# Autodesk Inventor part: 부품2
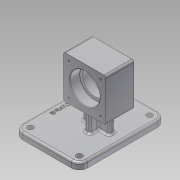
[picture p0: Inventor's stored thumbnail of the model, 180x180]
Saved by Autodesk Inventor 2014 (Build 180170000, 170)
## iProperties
Created: 2020-11
Part Number: 부품2
Material: 알루미늄 6061
Document SubType Name: Modeling
Designer: NET
Density: 2.71 g/cm^3
Appearance: 알루미늄 - 평지
Mass: 683.566 g
Surface Area: 546.675 cm^2
Volume: 252.238 cm^3
Author: NET
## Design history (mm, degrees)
sketch "스케치1"
  geometry: L1 (0, 0)-(64, 0); L2 (64, 0)-(64, 64); L3 (64, 64)-(0, 64); L4 (0, 64)-(0, 0)
  constraints: 8 end point, 2 parallel, 1 horizontal, 1 perpendicular
  dimensions: "d0" = 64 distance of L2.end L3.end; "d1" = 64 distance of L1.end L2.end
extrude "돌출1" new body sketch "스케치1" distance "d2" = 42; taper "d3" = 0 deg
sketch "스케치2"
  geometry: L1 (0, 0)-(0, 64) reference; L2 (0, 64)-(-64, 64) reference; L3 (-64, 64)-(-64, 0) reference; L4 (-64, 0)-(0, 0) reference; L5 (-32, 64)-(-32, 0); L6 (-64, 32)-(0, 32); C1 r 18 at (-32, 32)
  constraints: 5 midpoint, 4 end point, 1 centre point
  dimensions: "d4" = 36 diameter of C1
extrude "돌출2" cut sketch "스케치2" stored distance "d5" = 42; taper "d6" = 0 deg
sketch "스케치3"
  geometry: C1 r 18 at (-32, 32) reference; C2 r 22.5 at (-32, 32)
  constraints: 1 centre point, 1 coincident
  dimensions: "d7" = 45 diameter of C2
extrude "돌출3" cut sketch "스케치3" distance "d8" = 15; taper "d9" = 0 deg
sketch "스케치4"
  geometry: C1 r 18 at (32, 32) reference; C2 r 21 at (32, 32)
  constraints: 1 centre point, 1 coincident
  dimensions: "d10" = 42 diameter of C2
extrude "돌출4" cut sketch "스케치4" distance "d11" = 15; taper "d12" = 0 deg
node "작업 평면1"
sketch "스케치5"
  geometry: L1 (0, 0)-(0, 64) reference; L2 (0, 64)-(-42, 64) reference; L3 (-42, 0)-(-42, 64) reference; L4 (0, 0)-(-42, 0) reference; L5 (-21, 64)-(-21, 0); L6 (0, 32)-(-42, 32); L7 (44, -30)-(-86, -30); L8 (-86, -30)-(-86, 68); L9 (-86, 68)-(44, 68); L10 (44, 68)-(44, -30); L11 (44, -30)-(-86, 68); L12 (-86, -30)-(44, 68); 2 further points
  constraints: 16 end point, 6 midpoint, 2 parallel, 1 horizontal, 1 perpendicular, 1 point on line
  dimensions: "d14" = 130 distance of L8.end L9.end; "d15" = 98 distance of L7.end L8.end; "d16" = 62 vertical distance of L7.end L6.end
extrude "돌출5" join sketch "스케치5" distance "d17" = 10; taper "d18" = 0 deg
fillet "모깎기1" dims "d19" = 12
sketch "스케치6"
  geometry: C1 r 4.5 at (-74, 56); C2 r 4.5 at (-74, -18); C3 r 4.5 at (32, -18); C4 r 4.5 at (32, 56); A1 r 12 centre (32, -18) between (32, -30) and (44, -18) reference; A2 r 12 centre (32, 56) between (44, 56) and (32, 68) reference; A3 r 12 centre (-74, 56) between (-74, 68) and (-86, 56) reference; A4 r 12 centre (-74, -18) between (-86, -18) and (-74, -30) reference; 1 further point
  constraints: 4 centre point, 4 coincident
  dimensions: "d20" = 9 diameter of C1; "d21" = 9 diameter of C2; "d22" = 9 diameter of C3; "d23" = 9 diameter of C4
extrude "돌출6" cut sketch "스케치6" stored distance "d24" = 10; taper "d25" = 0 deg
sketch "스케치7"
  geometry: L1 (-56, 8)-(-8, 8); L2 (-8, 8)-(-8, 56); L3 (-8, 56)-(-56, 56); L4 (-56, 56)-(-56, 8); L5 (-56, 8)-(-8, 56); L6 (-8, 8)-(-56, 56); C1 r 22.5 at (-32, 32) reference; 6 further points
  constraints: 12 end point, 5 coincident, 3 midpoint, 2 parallel, 1 horizontal, 1 perpendicular
  dimensions: "d26" = 48 distance of L1.start L1.end; "d27" = 48 distance of L3.end L1.start
hole "구멍1" sketch "스케치7" at (-56, 56), (-8, 56), (-8, 8), (-56, 8) diameter "d28" = 2.459; stored, may be unused: countersink angle "d32" = 90 deg, drill point angle "d34" = 118 deg; dims "d29" = 8, "d30" = 4, "d31" = 2, "d33" = 10
sketch "스케치8"
  geometry: L1 (8, 8)-(56, 8); L2 (56, 8)-(56, 56); L3 (56, 56)-(8, 56); L4 (8, 56)-(8, 8); L5 (8, 8)-(56, 56); L6 (56, 8)-(8, 56); C1 r 21 at (32, 32) reference; 4 further points
  constraints: 12 end point, 4 coincident, 2 midpoint, 2 parallel, 1 horizontal, 1 perpendicular
  dimensions: "d35" = 48 distance of L3.end L1.start; "d36" = 48 distance of L2.end L3.end
hole "구멍2" sketch "스케치8" at (8, 56), (56, 56), (56, 8), (8, 8) diameter "d37" = 2.459; stored, may be unused: countersink angle "d41" = 90 deg, drill point angle "d43" = 118 deg; dims "d38" = 8, "d39" = 4, "d40" = 2, "d42" = 10
fillet "모깎기2" dims "d44" = 3
fillet "모깎기3" dims "d45" = 3
sketch "스케치9"
  geometry: L1 (83, 56)-(83, -18) reference; L2 (-32, 65)-(74, 65) reference; L3 (-41, -18)-(-41, 56) reference; L4 (74, -27)-(-32, -27) reference; L5 (21, -27)-(21, 65); L6 (-41, 32)-(83, 32); L7 (-32, -30)-(74, -30) reference; L8 (38, 28)-(4, 28); L9 (4, 28)-(4, 36); L10 (4, 36)-(38, 36); L11 (38, 36)-(38, 28); L12 (38, 28)-(4, 36); L13 (4, 28)-(38, 36); L14 (25, 52)-(17, 52); L15 (17, 52)-(17, 12); L16 (17, 12)-(25, 12); L17 (25, 12)-(25, 52); L18 (25, 52)-(17, 12); L19 (17, 52)-(25, 12); 3 further points
  constraints: 28 end point, 8 midpoint, 4 parallel, 3 perpendicular, 2 horizontal, 2 point on line
  dimensions: "d46" = 62 distance between parallel lines of L7 L6; "d47" = 8 distance of L15.end L16.end; "d48" = 8 distance of L8.end L9.end; "d49" = 34 distance of L9.end L10.end; "d50" = 40 distance of L14.end L15.end
extrude "돌출7" join sketch "스케치9" stored distance "d51" = 10; taper "d52" = 0 deg
fillet "모깎기4" dims "d53" = 3
fillet "모깎기5" dims "d54" = 3
fillet "모깎기6" dims "d55" = 0.3
chamfer "모따기1" distance "d56" = 1; stored, may be unused: second distance "d57" = 2, angle "d58" = 45 deg
sketch "스케치10"
  geometry: L1 (-32, 65)-(74, 65) reference; L2 (74, -27)-(-32, -27) reference; L3 (21, -27)-(21, 65); L4 (-44, 56)-(-44, -18) reference; L5 (-32, -30)-(74, -30) reference; 2 further points
  constraints: 2 end point, 2 midpoint, 1 other
  dimensions: "d59" = 65 distance from line of L4 point (21, -20); "d60" = 10 distance from line of L5 point (21, -20)
extrude "돌출8" join sketch "스케치10" distance "d61" = 0.5; taper "d62" = 0 deg
node "솔리드1"
node "투영된 루프1"
other parameters: "d13" = -38
